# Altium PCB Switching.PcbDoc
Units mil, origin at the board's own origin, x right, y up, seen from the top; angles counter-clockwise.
Board outline 6000 x 4000 mil, 2 copper layers (Top Layer, Bottom Layer); 23 components, 28 nets, 155 pads, 23 vias.
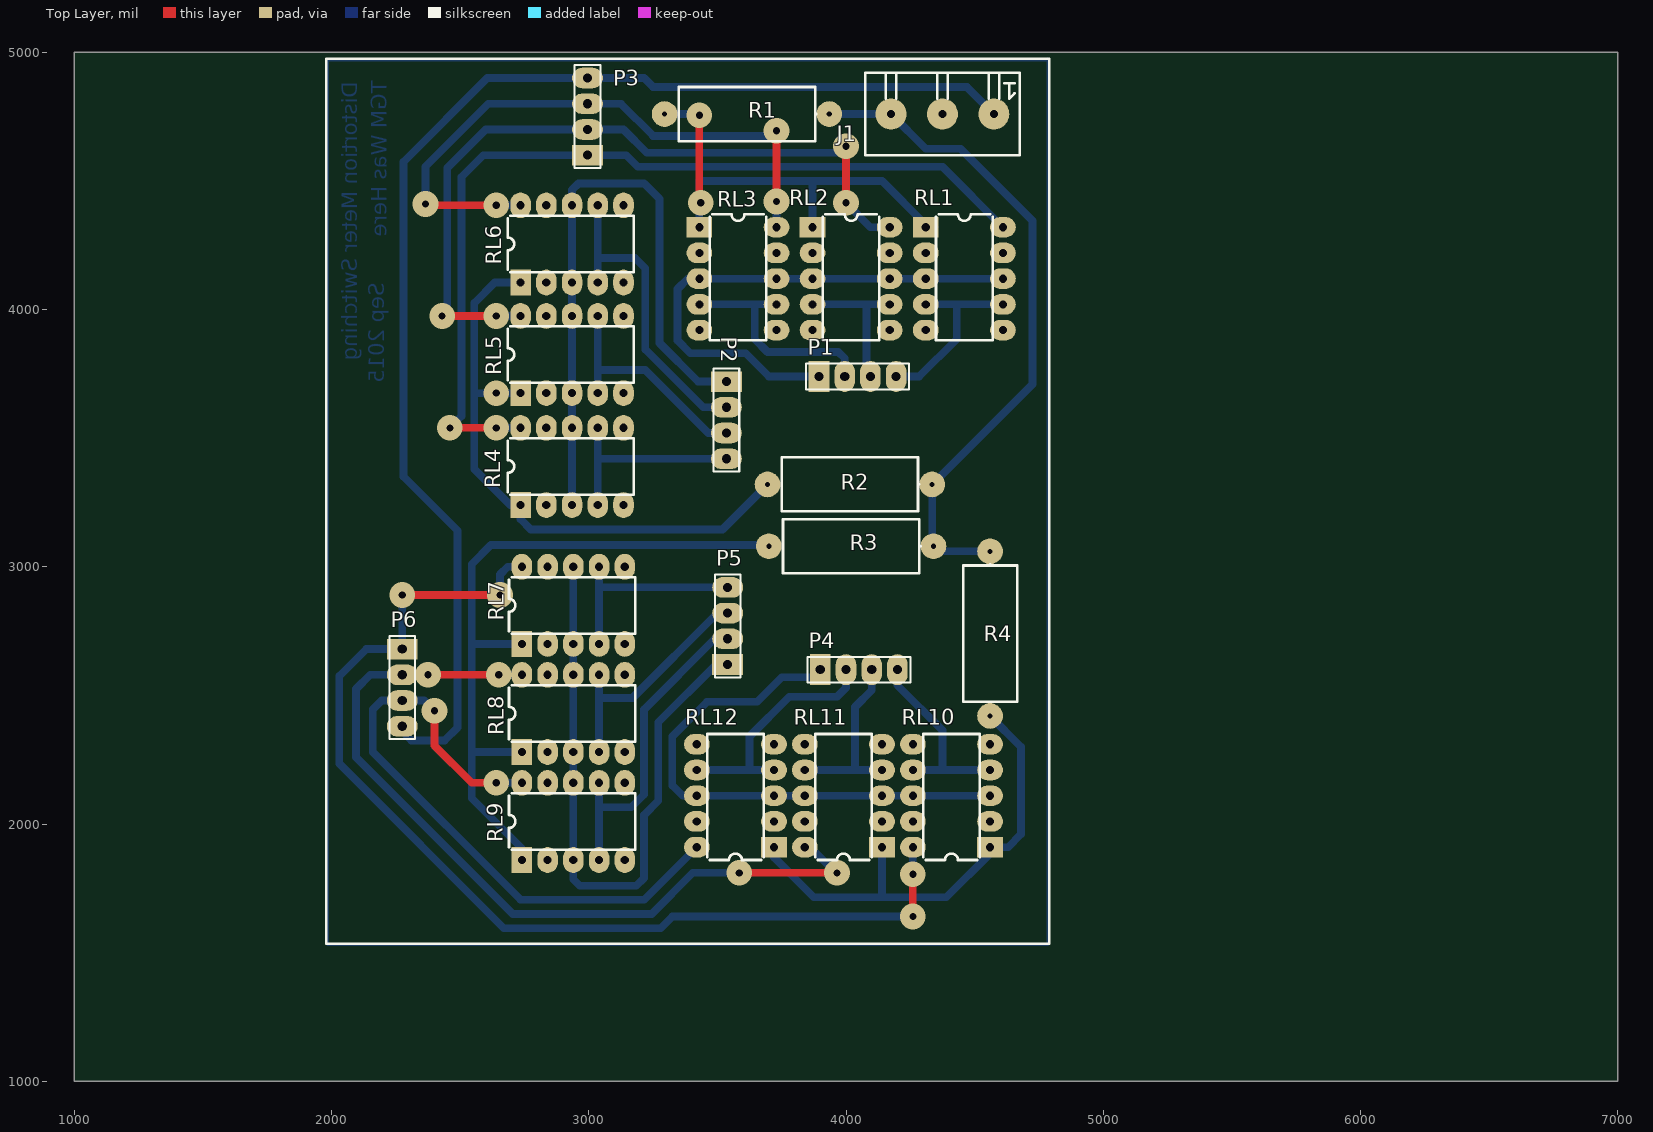
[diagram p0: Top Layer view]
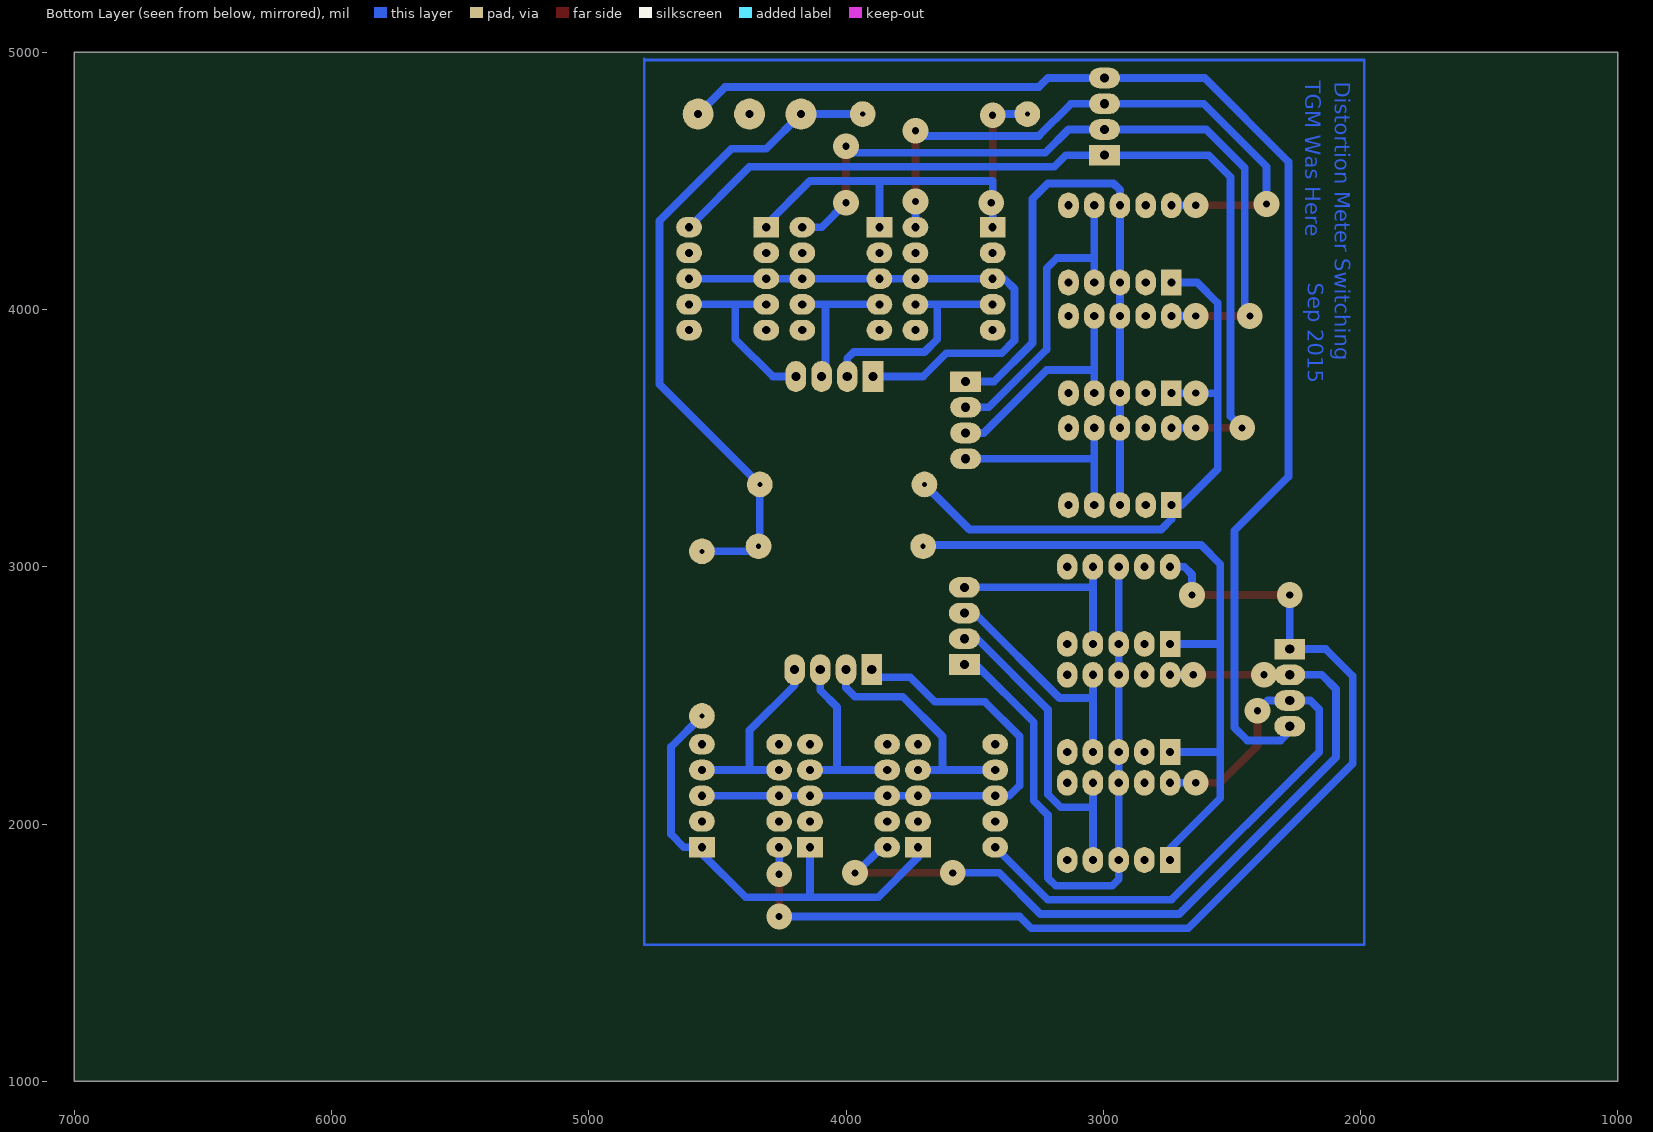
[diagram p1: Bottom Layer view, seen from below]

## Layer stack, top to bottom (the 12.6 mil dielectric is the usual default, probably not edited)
Top Layer: signal copper 1.4
Dielectric: dielectric 12.6, FR-4, Dk 4.8
Bottom Layer: signal copper 1.4

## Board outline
1000,1000 7000,1000 7000,5000 1000,5000

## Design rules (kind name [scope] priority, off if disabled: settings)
Clearance [All] p1: gap=10
PolygonConnect [All] p1: connectstyle=Relief reliefconductorwidth=10 reliefentries=4 polygonreliefangle="90 Angle"
RoutingVias [All] p1: holewidth=28 width=50 viastyle="Through Hole" minholewidth=28 minwidth=50 maxholewidth=28 maxwidth=50
SilkscreenOverComponentPads [All] p1: minsilkscreentomaskgap=10
SolderMaskExpansion [All] p1: expansion=4
Width [All] p1: maxlimit=255 minlimit=10 preferedwidth=30 minimp=50.000000 maximp=50.000000 favimp=50.000000
27 further rules are at their usual default settings.

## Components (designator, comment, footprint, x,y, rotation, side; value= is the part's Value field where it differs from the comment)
J1 "Input" CON3_SCREW 4375,4760 r90 top
P1 "Header 4" HDR1X4 3895,3740 r0 top
P2 "Header 4" HDR1X4 3535,3720 r270 top
P3 "Header 4" HDR1X4 2995,4600 r90 top
P4 "Header 4" HDR1X4 3900,2600 r0 top
P5 "Header 4" HDR1X4 3540,2620 r90 top
P6 "Header 4" HDR1X4 2275,2680 r270 top
R1 "RES2" AXIAL0.64 3935,4760 r180 top
R2 "RES2" AXIAL0.64 4335,3320 r180 top
R3 "RES2" AXIAL0.64 4340,3080 r180 top
R4 "RES2" AXIAL0.64 4560,3060 r270 top
RL1 "RELAY-DPDT_OMRON" DIP10 4310,4320 r0 top
RL2 "RELAY-DPDT_OMRON" DIP10 3870,4320 r0 top
RL3 "RELAY-DPDT_OMRON" DIP10 3430,4320 r0 top
RL4 "RELAY-DPDT_OMRON" DIP10 2735,3240 r90 top
RL5 "RELAY-DPDT_OMRON" DIP10 2735,3675 r90 top
RL6 "RELAY-DPDT_OMRON" DIP10 2735,4105 r90 top
RL7 "RELAY-DPDT_OMRON" DIP10 2740,2700 r90 top
RL8 "RELAY-DPDT_OMRON" DIP10 2740,2280 r90 top
RL9 "RELAY-DPDT_OMRON" DIP10 2740,1860 r90 top
RL10 "RELAY-DPDT_OMRON" DIP10 4560,1910 r180 top
RL11 "RELAY-DPDT_OMRON" DIP10 4140,1910 r180 top
RL12 "RELAY-DPDT_OMRON" DIP10 3720,1910 r180 top

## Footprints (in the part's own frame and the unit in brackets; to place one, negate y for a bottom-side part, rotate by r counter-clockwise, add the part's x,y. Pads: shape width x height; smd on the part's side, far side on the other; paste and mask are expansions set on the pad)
AXIAL0.64 [mil] "Matches 3W wirewould resistors in stock"
  round 100 hole 20: 1(0,0) 2(640,0)
  silkscreen extent 50,-105 585,105, body extent 50,-110 590,109, height 228
CON3_SCREW [mil]
  round 120 hole 30: 1(0,-200) 2(0,0) 3(0,200)
  silkscreen extent -160,-300 160,300, body extent -165,-305 165,305, height 250
DIP10 [mil]
  rect 100x80 hole 32: 1(0,0)
  oval 100x80 hole 32: 2(0,-100) 3(0,-200) 4(0,-300) 5(0,-400) 6(300,-400) 7(300,-300) 8(300,-200) 9(300,-100) 10(300,0)
  silkscreen extent 40,-440 260,50
HDR1X4 [mil] "Connector; Header; 4 Position"
  rect 80x120 hole 35.43: 1(0,0)
  oval 80x120 hole 35.43: 2(100,0) 3(200,0) 4(300,0)
  silkscreen extent -50,-50 350,50

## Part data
J1: library part CON3, "Connector"
P1 P2 P3 P4 P5 P6: "Header, 4-Pin"

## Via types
v1: diameter 100, hole 28, Top Layer to Bottom Layer, 23 vias

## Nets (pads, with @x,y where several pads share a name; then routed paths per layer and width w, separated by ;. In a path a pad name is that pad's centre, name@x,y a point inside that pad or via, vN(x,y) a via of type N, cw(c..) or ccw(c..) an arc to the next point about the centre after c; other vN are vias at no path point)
+VE: J1.3 R1.1 R2.1 R3.1 R4.1 | length 2618.8
  Bottom Layer w30: R1.1 J1.3 4310,4625 4445,4625 4725,4345 4725,3710 R2.1 4335,3085 4360,3060 R4.1
GND: J1.1 P3.4 P6.4 | length 5044.8
  Bottom Layer w30: P6.4 2275,2360 2310,2325 2440,2325 2490,2375 2490,3140 2280,3350 2280,4575 2605,4900 P3.4 3215,4900 3250,4865 4470,4865 J1.1
NetP1_1: P1.1 RL1.3 RL1.8 RL2.3 RL2.8 RL3.3 RL3.8 | length 2110.8
  Bottom Layer w30: P1.1@3880,3715 P1.1@3895,3700 ; P1.1 3700,3740 3610,3830 3395,3830 3345,3880 3345,4080 3385,4120 RL3.8 RL2.3 RL2.8 RL1.3 RL1.8
NetP1_2: P1.2 RL3.4 RL3.7 | length 906.1
  Bottom Layer w30: RL3.4 3645,4020 ; RL3.7 3645,4020 ; P1.2@3995,3720 3995,3810 3970,3835 3695,3835 3645,3885 3645,4020
NetP1_3: P1.3 RL2.4 RL2.7 | length 621.2
  Bottom Layer w30: RL2.4 RL2.7 ; 4080,4015 4080,3715 P1.3@4095,3700
NetP1_4: P1.4 RL1.4 RL1.7 | length 730.1
  Bottom Layer w30: P1.4 4285,3740 4430,3885 4430,4020 ; RL1.4 4430,4020 ; RL1.7 4430,4020
NetP2_1: P2.1 RL4.3 RL4.8 RL5.3 RL5.8 RL6.3 RL6.8 | length 2522.3
  Bottom Layer w30: RL4.3 RL6.3 ; RL6.3@2935,4065 RL6.3 ; P2.1 3425,3720 3275,3870 3275,4430 3215,4490 2960,4490 2935,4465 RL6.8 2935,4315 RL6.3
NetP2_2: P2.2 RL6.4 RL6.7 | length 1224.8
  Bottom Layer w30: RL6.4 3035,4200 ; RL6.7 3035,4200 ; P2.2 3445,3620 3220,3845 3220,4160 3180,4200 3035,4200
NetP2_3: P2.3 RL5.4 RL5.7 | length 871.5
  Bottom Layer w30: RL5.4@3035,3705 3035,3765 ; RL5.7 3035,3765 ; P2.3 3465,3520 3220,3765 3035,3765
NetP2_4: P2.4 RL4.4 RL4.7 | length 800
  Bottom Layer w30: RL4.4 3035,3420 ; RL4.7 3035,3420 ; P2.4 3035,3420
NetP3_1: P3.1 RL1.10 RL4.10 | length 3524.8
  Top Layer w30: v1(2460,3540) v1(2640,3540)
  Bottom Layer w30: v1(2460,3540) 2505,3585 2505,4515 2590,4600 P3.1 3145,4600 3190,4555 4375,4555 RL1.10 ; v1(2640,3540) RL4.10
NetP3_2: P3.2 RL2.10 RL5.10 | length 3032.8
  Top Layer w30: v1(2430,3975) v1(2640,3975) ; v1(4000,4415) v1(4000,4635)
  Bottom Layer w30: v1@2450,3975 v1(2430,3975) 2450,3995 2450,4550 2600,4700 P3.2 3135,4700 3225,4610 3975,4610 v1(4000,4635) v1@3975,4660 ; v1(2640,3975) RL5.10 ; v1(4000,4415) 4095,4320 RL2.10
NetP3_3: P3.3 RL3.10 RL6.10 | length 2431.5
  Top Layer w30: v1@2360,4405 v1(2640,4405) ; v1(3730,4420) v1(3730,4695)
  Bottom Layer w30: v1@2365,4400 2365,4555 2610,4800 P3.3 3125,4800 3250,4675 3710,4675 v1(3730,4695) ; v1(2640,4405) RL6.10 ; RL3.10 v1(3730,4420)
  other v1: 2365,4410
NetP4_1: P4.1 RL10.3 RL10.8 RL11.3 RL11.8 RL12.3 RL12.8 | length 2124.3
  Bottom Layer w30: P4.1 3870,2570 3750,2570 3655,2475 3460,2475 3325,2340 3325,2150 3365,2110 RL12.8 RL12.3 RL11.8 RL11.3 RL10.8 RL10.3
NetP4_2: P4.2 RL12.4 RL12.7 | length 953.7
  Bottom Layer w30: RL12.7 3625,2210 ; RL12.4 3625,2210 ; P4.2 4000,2530 3965,2495 3780,2495 3625,2340 3625,2210
NetP4_3: P4.3 RL11.4 RL11.7 | length 716.9
  Bottom Layer w30: RL11.7 4035,2210 ; P4.3 4100,2520 4035,2455 4035,2210 ; RL11.4 4035,2210
NetP4_4: P4.4 RL10.4 RL10.7 | length 757.5
  Bottom Layer w30: P4.4 4200,2540 4375,2365 4375,2215 ; RL10.7 RL10.4
NetP5_1: P5.1 RL7.3 RL7.8 RL8.3 RL8.8 RL9.3 RL9.8 | length 2503.8
  Bottom Layer w30: RL7.8 RL7.3 RL8.8 RL8.3 RL9.8 RL9.3 2940,1785 2965,1760 3185,1760 3215,1790 3215,2035 3270,2090 3270,2395 3495,2620 P5.1
NetP5_2: P5.2 RL9.4 RL9.7 | length 1264.6
  Bottom Layer w30: RL9.4 3040,2065 ; RL9.7 3040,2065 ; P5.2 3490,2720 3215,2445 3215,2115 3165,2065 3040,2065
NetP5_3: P5.3 RL8.4 RL8.7 | length 936.7
  Bottom Layer w30: RL8.4 3040,2490 ; RL8.7 3040,2490 ; P5.3 3500,2820 3170,2490 3040,2490
NetP5_4: P5.4 RL7.4 RL7.7 | length 790
  Bottom Layer w30: RL7.4 RL7.7 ; 3050,2920 P5.4
NetP6_1: P6.1 RL7.10 RL10.10 | length 4184.7
  Top Layer w30: v1@2270,2890 v1(2275,2890) v1(2655,2890) ; v1(4260,1640) v1(4260,1805)
  Bottom Layer w30: v1(2275,2890) P6.1 2135,2680 2030,2575 2030,2235 2670,1595 3280,1595 3325,1640 v1(4260,1640) ; v1(2655,2890) 2655,2970 2685,3000 RL7.10 ; v1(4260,1805) RL10.10
NetP6_2: P6.2 RL8.10 RL11.10 | length 3293.1
  Top Layer w30: v1(2375,2580) v1(2650,2580) ; v1(3585,1810) v1(3965,1810)
  Bottom Layer w30: v1(2375,2580) P6.2 2150,2580 2095,2525 2095,2260 2705,1650 3245,1650 3405,1810 v1(3585,1810) ; v1(2650,2580) RL8.10 ; RL11.10 3860,1910 3960,1810 v1(3965,1810) v1@3970,1810
NetP6_3: P6.3 RL9.10 RL12.10 | length 2559.2
  Top Layer w30: v1(2400,2440) 2400,2305 2545,2160 v1(2640,2160)
  Bottom Layer w30: P6.3@2270,2480 P6.3 ; v1(2400,2440) 2360,2480 P6.3 ; v1(2640,2160) RL9.10 ; RL12.10 3215,1705 2735,1705 2160,2280 2160,2445 2195,2480 P6.3
NetR1_2: R1.2 RL1.1 RL2.1 RL3.1 | length 1832.5
  Top Layer w30: v1@3430,4415 v1(3430,4755)
  Bottom Layer w30: R1.2 3425,4760 v1(3430,4755) ; RL3.1 3430,4500 3870,4500 ; RL2.1 3870,4500 ; RL1.1@4345,4320 RL1.1 4310,4330 4140,4500 3870,4500
  other v1: 3435,4415
NetR2_2: R2.2 RL4.1 RL5.1 RL6.1 | length 2375.2
  Bottom Layer w30: 2560,3675 v1(2640,3675) RL5.1 ; RL6.1 2635,4105 2555,4025 2555,3380 2695,3240 RL4.1 2735,3185 2775,3145 3520,3145 R2.2
NetR3_2: R3.2 RL7.1 RL8.1 RL9.1 | length 2808.9
  Bottom Layer w30: RL9.1 2740,1905 2545,2100 2545,2280 ; RL8.1 2545,2280 ; RL7.1 2545,2700 ; R3.2 3695,3085 2620,3085 2545,3010 2545,2700 ; 2545,2280 2545,2700
NetR4_2: R4.2 RL10.1 RL11.1 RL12.1 | length 1885
  Bottom Layer w30: RL12.1 3720,1870 3875,1715 4140,1715 ; RL11.1 4140,1715 ; R4.2 4680,2300 4680,1960 4630,1910 RL10.1 4560,1885 4390,1715 4140,1715
pads on no net: J1.2 RL1.2 RL1.5 RL1.6 RL1.9 RL2.2 RL2.5 RL2.6 RL2.9 RL3.2 RL3.5 RL3.6 RL3.9 RL4.2 RL4.5 RL4.6 RL4.9 RL5.2 RL5.5 RL5.6 RL5.9 RL6.2 RL6.5 RL6.6 RL6.9 RL7.2 RL7.5 RL7.6 RL7.9 RL8.2 RL8.5 RL8.6 RL8.9 RL9.2 RL9.5 RL9.6 RL9.9 RL10.2 RL10.5 RL10.6 RL10.9 RL11.2 RL11.5 RL11.6 RL11.9 RL12.2 RL12.5 RL12.6 RL12.9
copper on no net: | length 12485
  Bottom Layer w10: 4785,4970 1985,4970 1985,1530 4785,1530 4785,4975

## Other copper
Bottom Layer:
  text "TGM Was Here" at 2215,4890 h60 r90
  text "Distortion Meter Switching" at 2100,4885 h60 r90
  text "Sep 2015" at 2205,4105 h60 r90

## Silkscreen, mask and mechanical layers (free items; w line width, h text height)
Top Overlay:
  lines w10: 1980,1535 1980,4975 4790,4975 4790,4745 4790,1535 1980,1535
